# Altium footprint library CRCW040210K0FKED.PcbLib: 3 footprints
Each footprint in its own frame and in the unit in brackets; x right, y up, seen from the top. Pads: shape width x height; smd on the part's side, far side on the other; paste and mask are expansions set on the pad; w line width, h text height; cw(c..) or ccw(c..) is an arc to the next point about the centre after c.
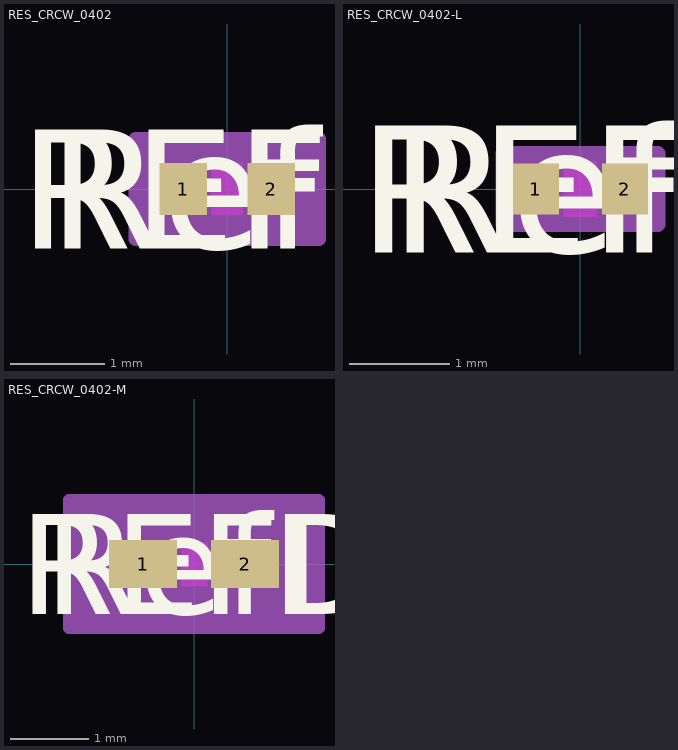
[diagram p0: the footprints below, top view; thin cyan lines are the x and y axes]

## RES_CRCW_0402 [mil]
pads (2):
  rect 20x22 smd paste-11 mask-11: 1(-18.5,0) 2(18.5,0)
Top Layer keep-out:
  region: -6.5,-9 -6.5,9 6.5,9 6.5,-9
Top Overlay:
  text "RefDes" at -75,-25 h50
  text "REFDES" at -87.5,-25 h50
Keep-Out Layer:
  region: -6.5,-11 -6.5,11 6.5,11 6.5,-11
Mechanical 13:
  lines w1: -20.5,-11 -20.5,11 ; -20.5,-11 -8.5,-11 -8.5,11 -20.5,11 ; -20.5,-11 20.5,-11 ; -20.5,-11 -20.5,11 ; -20.5,11 20.5,11 ; 20.5,-11 8.5,-11 8.5,11 20.5,11 ; 20.5,-11 20.5,11 ; 20.5,-11 20.5,11
  text "RefDes2" at -87.5,-25 h50
Mechanical 15:
  region: 38.5,-21 -38.5,-21 -38.5,21 38.5,21
  lines w6: -38.5,-21 -38.5,21 38.5,21 38.5,-21 -38.5,-21
3D body "RES_CRCW_0402.step": height 15.98, standoff 0, extent -20.51,-10.98 20.51,10.98

## RES_CRCW_0402-L [mil]
pads (2):
  rect 18x20 smd paste+0 mask+0: 1(-17.5,0) 2(17.5,0)
Top Layer keep-out:
  region: -6.5,-9 -6.5,9 6.5,9 6.5,-9
Top Overlay:
  text "RefDes" at -75,-25 h50
  text "REFDES" at -87.5,-25 h50
Keep-Out Layer:
  region: -6.5,-11 -6.5,11 6.5,11 6.5,-11
Mechanical 13:
  lines w1: -20.5,-11 -20.5,11 ; -20.5,-11 -8.5,-11 -8.5,11 -20.5,11 ; -20.5,-11 20.5,-11 ; -20.5,-11 -20.5,11 ; -20.5,11 20.5,11 ; 20.5,-11 8.5,-11 8.5,11 20.5,11 ; 20.5,-11 20.5,11 ; 20.5,-11 20.5,11
  text "RefDes2" at -87.5,-25 h50
Mechanical 15:
  region: 30.5,-14 -30.5,-14 -30.5,14 30.5,14
  lines w6: -30.5,-14 -30.5,14 30.5,14 30.5,-14 -30.5,-14
3D body "RES_CRCW_0402.step": height 15.98, standoff 0, extent -20.51,-10.98 20.51,10.98

## RES_CRCW_0402-M [mil]
pads (2):
  rect 34x24 smd paste+0 mask+0: 1(-25.5,0) 2(25.5,0)
Top Layer keep-out:
  region: -6.5,-9 -6.5,9 6.5,9 6.5,-9
Top Overlay:
  text "RefDes" at -75,-25 h50
  text "REFDES" at -87.5,-25 h50
Keep-Out Layer:
  region: -6.5,-11 -6.5,11 6.5,11 6.5,-11
Mechanical 13:
  lines w1: -20.5,-11 -20.5,11 ; -20.5,-11 -8.5,-11 -8.5,11 -20.5,11 ; -20.5,-11 20.5,-11 ; -20.5,-11 -20.5,11 ; -20.5,11 20.5,11 ; 20.5,-11 8.5,-11 8.5,11 20.5,11 ; 20.5,-11 20.5,11 ; 20.5,-11 20.5,11
  text "RefDes2" at -87.5,-25 h50
Mechanical 15:
  region: 62.5,-32 -62.5,-32 -62.5,32 62.5,32
  lines w6: -62.5,-32 -62.5,32 62.5,32 62.5,-32 -62.5,-32
3D body "RES_CRCW_0402.step": height 15.98, standoff 0, extent -20.51,-10.98 20.51,10.98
